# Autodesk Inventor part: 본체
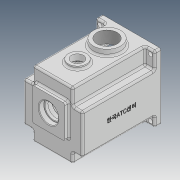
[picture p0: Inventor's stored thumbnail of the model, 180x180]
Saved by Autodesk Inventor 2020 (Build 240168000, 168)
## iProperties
Created: 2022-01
Part Number: 본체
Material: 일반
Document SubType Name: Modeling
Designer: user
Density: 1 g/cm^3
Appearance: 기본값
Author: user
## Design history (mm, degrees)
sketch "스케치2"
  geometry: L1 (-49, 55)-(49, 55); L2 (49, 55)-(49, -55); L3 (49, -55)-(-49, -55); L4 (-49, -55)-(-49, 55); L5 (-49, 55)-(49, -55); L6 (49, 55)-(-49, -55); 1 further point
  constraints: 12 end point, 2 midpoint, 2 parallel, 1 horizontal, 1 perpendicular
  dimensions: "d4" = 98 distance of L2.end L3.end; "d5" = 110 distance of L1.end L2.end
extrude "돌출2" new body sketch "스케치2" distance "d6" = 130; taper "d7" = 0 deg
sketch "스케치3"
  geometry: L1 (-49, 55)-(-33, 55); L2 (-33, 55)-(-33, 28); L3 (-33, 28)-(-49, 28); L4 (-49, 28)-(-49, 55); L5 (49, 55)-(33, 55); L6 (33, 55)-(33, 28); L7 (33, 28)-(49, 28); L8 (49, 28)-(49, 55); 1 further point
  constraints: 16 end point, 4 parallel, 2 horizontal, 2 perpendicular
  dimensions: "d8" = 16 distance of L1.start L1.end; "d9" = 16 distance of L5.start L5.end; "d10" = 27 distance of L7.end L5.start; "d11" = 27 distance of L1.end L2.end
extrude "돌출3" cut sketch "스케치3" distance "d12" = 120; taper "d13" = 0 deg
sketch "스케치4"
  geometry: L1 (-49, -55)-(49, -55) reference; L2 (-49, -55)-(-33, -55); L3 (-33, -55)-(-33, -38); L4 (-33, -38)-(-49, -38); L5 (-49, -38)-(-49, -55); L6 (49, -55)-(33, -55); L7 (33, -55)-(33, -38); L8 (33, -38)-(49, -38); L9 (49, -38)-(49, -55); 3 further points
  constraints: 16 end point, 4 parallel, 2 horizontal, 2 perpendicular, 1 point on line
  dimensions: "d14" = 16 distance of L3.end L4.end; "d15" = 16 distance of L7.end L8.end; "d16" = 17 distance of L6.end L7.end
extrude "돌출4" cut sketch "스케치4" distance "d17" = 120; taper "d18" = 0 deg
node "작업 평면1"
sketch "스케치6"
  geometry: L1 (0, 0)-(0, 40); L2 (0, 40)-(0, 89); C1 r 22.5 at (0, 40)
  constraints: 4 end point, 2 vertical, 1 centre point, 1 coincident
  dimensions: "d24" = 40 distance of L1.start L1.end; "d25" = 45 diameter of C1; "d26" = 49 distance of L2.start L2.end
extrude "돌출6" join sketch "스케치6" stored distance "d28" = 7; taper "d29" = 0 deg
node "작업 평면2"
sketch "스케치7"
  geometry: L1 (0, 0)-(0, 40); L2 (0, 40)-(0, 89); C1 r 15 at (0, 89)
  constraints: 4 end point, 1 centre point, 1 coincident, 1 point on line, 1 vertical
  dimensions: "d31" = 40 distance of L1.start L1.end; "d32" = 49 distance of L1.end L2.end; "d33" = 30 diameter of C1
extrude "돌출7" join sketch "스케치7" stored distance "d34" = 7; taper "d35" = 0 deg
sketch "스케치8"
  geometry: L1 (49, -55)-(-49, -55) reference; L2 (-23, 45)-(23, 45); L3 (23, 45)-(23, -5); L4 (23, -5)-(-23, -5); L5 (-23, -5)-(-23, 45); L6 (-49, 55)-(49, 55) reference; L7 (-49, -55)-(-49, 55) reference; L8 (49, -55)-(-49, -55) reference; L9 (49, 55)-(49, -55) reference; L10 (-49, 55)-(49, 55) reference; C1 r 42 at (0, -5); 6 further points
  constraints: 8 end point, 4 midpoint, 2 parallel, 2 vertical alignment, 1 centre point, 1 coincident, 1 horizontal, 1 perpendicular
  dimensions: "d38" = 50 distance from line of L1 C1.centre; "d39" = 84 diameter of C1; "d40" = 50 distance of C1.centre point (0, 45); "d41" = 46 distance between parallel lines of L5 L3
extrude "돌출8" cut sketch "스케치8" distance "d42" = 121; taper "d43" = 0 deg
sketch "스케치10"
  geometry: L1 (-23, 45)-(23, 45) reference; L2 (-23, 30.143)-(-23, 45) reference; L3 (23, 45)-(23, 30.143) reference; L4 (-26, 31.729)-(-26, 48); L5 (-26, 48)-(26, 48); L6 (26, 48)-(26, 31.729); A1 r 42 centre (0, -5) between (-23, 30.143) and (23, 30.143) reference; A2 r 45 centre (0, -5) between (-26, 31.729) and (26, 31.729); 1 further point
  constraints: 6 end point, 2 point on circle, 1 centre point, 3 other
  dimensions: "d50" = 3 radial gap between concentric circles of A1 A2
extrude "돌출10" cut sketch "스케치10" distance "d51" = 9; taper "d52" = 0 deg
sketch "스케치11"
  geometry: C1 r 22.5 at (0, 0) reference; 2 further points
  constraints: 1 coincident
hole "구멍1" sketch "스케치11" at (0, 0) diameter "d53" = 33.376; stored, may be unused: countersink angle "d57" = 90 deg, drill point angle "d59" = 0 deg; dims "d54" = 70, "d55" = 4, "d56" = 2, "d58" = 77.3
sketch "스케치12"
  geometry: L1 (-27, 33)-(27, 33); L2 (27, 33)-(27, -21); L3 (27, -21)-(-27, -21); L4 (-27, -21)-(-27, 33); L5 (-27, 33)-(27, -21); L6 (27, 33)-(-27, -21); L7 (-33, -55)-(33, -55) reference; 3 further points
  constraints: 12 end point, 3 midpoint, 2 parallel, 1 horizontal, 1 perpendicular, 1 vertical alignment
  dimensions: "d60" = 54 distance of L2.end L3.end; "d61" = 54 distance of L1.end L2.end; "d62" = 61 distance from line of L7 point (0, 6)
extrude "돌출11" join sketch "스케치12" distance "d63" = 7; taper "d64" = 0 deg
sketch "스케치13"
  geometry: C1 r 15 at (0, 0) reference; 2 further points
  constraints: 1 coincident
hole "구멍2" sketch "스케치13" at (0, 0) diameter "d65" = 20; stored, may be unused: countersink angle "d69" = 90 deg, drill point angle "d71" = 0 deg; dims "d66" = 70, "d67" = 4, "d68" = 2, "d70" = 51.3
sketch "스케치15"
  geometry: C1 r 10 at (23, -32) reference; C2 r 15 at (23, -32); 1 further point
  constraints: 1 centre point, 1 coincident
  dimensions: "d72" = 30 diameter of C2
extrude "돌출12" cut sketch "스케치15" distance "d73" = 5; taper "d74" = 0 deg
chamfer "모따기1" distance "d75" = 1; stored, may be unused: second distance "d76" = 2, angle "d77" = 45 deg
sketch "스케치21"
  geometry: L1 (0, 6)-(0, -25); A1 r 21 centre (0, 6) between (8.978, -12.984) and (-8.978, -12.984); A2 r 15 centre (0, -25) between (-8.978, -12.984) and (8.978, -12.984); 1 further point
  constraints: 4 point on circle, 2 centre point, 2 coincident, 2 end point, 1 vertical
  dimensions: "d92" = 42 diameter of A1; "d93" = 31 distance of L1.start L1.end; "d94" = 30 diameter of A2
extrude "돌출16" join sketch "스케치21" distance "d95" = 7; taper "d96" = 0 deg
sketch "스케치22"
  geometry: A1 r 21 centre (0, 6) between (8.978, -12.984) and (-8.978, -12.984) reference; 2 further points
  constraints: 1 coincident
hole "구멍3" sketch "스케치22" at (0, 6) diameter "d97" = 28; stored, may be unused: countersink angle "d101" = 90 deg, drill point angle "d103" = 0 deg; dims "d98" = 70, "d99" = 35, "d100" = 10, "d102" = 51.3
sketch "스케치23"
  geometry: C1 r 14 at (0, 6) reference; C2 r 16 at (0, 6); 1 further point
  constraints: 1 centre point, 1 coincident
  dimensions: "d104" = 32 diameter of C2
extrude "돌출17" cut sketch "스케치23" distance "d105" = 8.3; taper "d106" = 0 deg
sketch "스케치25"
  geometry: A1 r 15 centre (0, -25) between (-8.978, -12.984) and (8.978, -12.984) reference; 2 further points
  constraints: 1 coincident
hole "구멍4" sketch "스케치25" at (0, -25) diameter "d107" = 19; stored, may be unused: countersink angle "d111" = 90 deg, drill point angle "d113" = 0 deg; dims "d108" = 70, "d109" = 22, "d110" = 7, "d112" = 10
chamfer "모따기2" distance "d114" = 1; stored, may be unused: second distance "d115" = 2, angle "d116" = 45 deg
sketch "스케치26"
  geometry: L1 (-36, -5)-(36, -5); L2 (-36, -1)-(-41.809, -1); L3 (-35.778, -8.994)-(-41.81, -8.994); L4 (35.778, -1.006)-(41.81, -1.006); L5 (35.778, -8.994)-(41.81, -8.994); A1 r 42 centre (0, -5) between (-23, 30.143) and (23, 30.143) reference; A2 r 36 centre (0, -5) between (-36, -5) and (36, -5); A3 r 4 centre (-36, -5) between (-36, -1) and (-35.778, -8.994); A4 r 4 centre (36, -5) between (35.778, -1.006) and (35.778, -8.994); A5 r 42 centre (0, -5) between (-23, 30.143) and (23, 30.143) reference; 8 further points
  constraints: 14 point on circle, 10 end point, 4 horizontal, 3 centre point, 2 coincident, 1 parallel
  dimensions: "d119" = 72 diameter of A2; "d120" = 8 diameter of A3; "d121" = 8 diameter of A4
extrude "돌출18" join sketch "스케치26" stored distance "d122" = 7; taper "d123" = 0 deg
sketch "스케치27"
  geometry: A1 r 4 centre (-36, -5) between (-36.222, -8.994) and (-36, -1) reference; A2 r 4 centre (36, -5) between (36.222, -1.006) and (36.222, -8.994) reference; 3 further points
  constraints: 2 coincident
hole "구멍5" sketch "스케치27" at (-36, -5), (36, -5) diameter "d124" = 3.242; stored, may be unused: countersink angle "d128" = 90 deg, drill point angle "d130" = 118 deg; dims "d125" = 7, "d126" = 22, "d127" = 7, "d129" = 9
fillet "모깎기3" dims "d131" = 3
fillet "모깎기4" dims "d132" = 3
fillet "모깎기5" dims "d133" = 3
fillet "모깎기6" dims "d134" = 3
fillet "모깎기7" dims "d135" = 3
fillet "모깎기8" dims "d136" = 3
fillet "모깎기9" dims "d137" = 3
fillet "모깎기10" dims "d138" = 3
fillet "모깎기11" dims "d139" = 3
fillet "모깎기12" dims "d140" = 3
fillet "모깎기13" dims "d144" = 0.3
fillet "모깎기14" dims "d145" = 6
fillet "모깎기15" dims "d146" = 3
fillet "모깎기16" dims "d147" = 3
fillet "모깎기17" dims "d148" = 6
chamfer "모따기4" distance "d149" = 1; stored, may be unused: second distance "d150" = 2, angle "d151" = 30 deg
fillet "모깎기18" dims "d152" = 3
fillet "모깎기19" dims "d153" = 3
fillet "모깎기20" dims "d154" = 3
fillet "모깎기21" dims "d155" = 3
sketch "스케치28"
  geometry: L1 (-49, -52)-(-49, 52) reference; L2 (-46, 55)-(46, 55) reference; L3 (-42, 48)-(-42, -48); L4 (0, 55)-(0, -55); 4 further points
  constraints: 4 end point, 2 symmetric about line, 2 vertical, 1 coincident, 1 midpoint
  dimensions: "d157" = 7 distance from line of L1 L3.start; "d158" = 7 distance from line of L2 L3.start; "d159" = 96 distance of L3.start L3.end
hole "구멍6" sketch "스케치28" at (-42, 48), (-42, -48), (42, 48), (42, -48) diameter "d160" = 7; stored, may be unused: countersink angle "d164" = 90 deg, drill point angle "d166" = 118 deg; dims "d161" = 7, "d162" = 22, "d163" = 7, "d165" = 9
sketch "스케치30"
  geometry: L1 (-3, 87)-(-3, 66) reference; L2 (114, 90)-(0, 90) reference; L3 (114, 63)-(0, 63) reference; 2 further points
  constraints: 1 other
  dimensions: "d167" = 65 distance from line of L1 point (62, 30); "d173" = 27 distance between parallel lines of L3 L2 (derived); "d174" = 33 distance from line of point (62, 30) L3
feature "엠보싱1" sketch "스케치30" dims "d171" = 0.5, "d172" = 0
fillet "모깎기23" dims "d176" = 0.3
fillet "모깎기24" dims "d177" = 3
chamfer "모따기5" distance "d178" = 0.8; stored, may be unused: second distance "d179" = 2, angle "d180" = 60 deg
node "솔리드2"
node "투영된 루프1"
node "투영된 루프2"
feature "A9D066F2-1C7D-4E18-AEED-F7BC21143FA4" dims "d65" = 20, "d66" = 70, "d67" = 4, "d68" = 2, "d69" = 90 deg, "d70" = 51.3, "d71" = 0
other parameters: "d23" = 65, "d30" = -5
